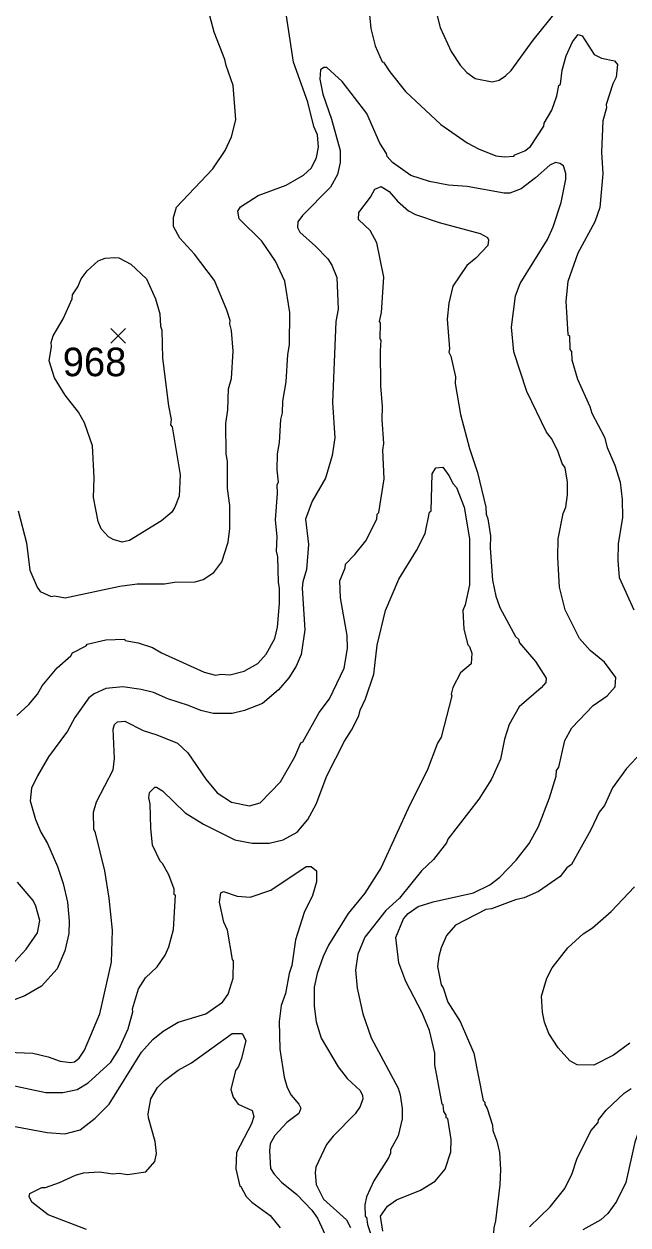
# Model space of a CAD drawing. Extents: x 265.7 to 292.1, y 7676.2 to 7704.2.
# Drawn here: x 276.788 to 278.481, y 7696.84 to 7700.203 of the extents above; entities that cross this region are included whole.
import ezdxf
from ezdxf.enums import TextEntityAlignment as Align

# ---------------------------------------------------------------- set-up
doc = ezdxf.new("R2010")
doc.units = 0
doc.header["$LTSCALE"] = 0.032
for name, color, linetype, lineweight in [('1', 7, 'Continuous', 25), ('2', 7, 'Continuous', 13), ('21', 7, 'Continuous', 25)]:
    doc.layers.add(name, color=color, linetype=linetype, lineweight=lineweight)
doc.layers.add('61', color=7, linetype='Continuous')

msp = doc.modelspace()

# ---------------------------------------------------------------- linework, layer by layer
at = {"layer": '1'}
for points in [[(278.3115, 7698.9198), (278.3051, 7698.9605), (278.2971, 7698.9725), (278.2844, 7699.0076), (278.2668, 7699.0427), (278.2532, 7699.0602), (278.1982, 7699.1735), (278.1615, 7699.2853), (278.1551, 7699.3539), (278.1663, 7699.4417), (278.179, 7699.4768), (278.2556, 7699.5997), (278.2716, 7699.6348), (278.2939, 7699.7034), (278.3067, 7699.7688), (278.3067, 7699.7848), (278.3003, 7699.8063), (278.2907, 7699.8127), (278.278, 7699.8151), (278.262, 7699.8079), (278.2221, 7699.772), (278.1822, 7699.7417), (278.1503, 7699.7297), (278.1344, 7699.7289), (278.0306, 7699.7481), (277.978, 7699.752), (277.9253, 7699.7616), (277.8726, 7699.7792), (277.8216, 7699.8151), (277.8064, 7699.8319), (277.804, 7699.8406), (277.7856, 7699.8694), (277.7489, 7699.9524), (277.6803, 7700.0417), (277.6372, 7700.0816), (277.6284, 7700.0816), (277.6197, 7700.0744), (277.6173, 7700.0489), (277.626, 7700.0066), (277.65, 7699.9364), (277.6747, 7699.8486), (277.6747, 7699.8151), (277.6667, 7699.7816), (277.6476, 7699.7465), (277.5686, 7699.6667), (277.5558, 7699.6491), (277.555, 7699.6332), (277.5614, 7699.6204), (277.6053, 7699.5813), (277.6396, 7699.5454), (277.6508, 7699.5278), (277.6651, 7699.4927), (277.6691, 7699.4049), (277.662, 7699.3698), (277.6532, 7699.1432), (277.6596, 7699.0443), (277.6524, 7698.9948), (277.6332, 7698.931), (277.5957, 7698.8671), (277.5774, 7698.8161), (277.5853, 7698.7458), (277.5806, 7698.6756), (277.5694, 7698.6405), (277.5678, 7698.6229), (277.5758, 7698.5064), (277.5654, 7698.4378), (277.551, 7698.4043), (277.5303, 7698.3724), (277.5016, 7698.3381), (277.4569, 7698.3006), (277.4066, 7698.2806), (277.3715, 7698.2726), (277.3188, 7698.2726), (277.2837, 7698.2806), (277.2494, 7698.295), (277.1912, 7698.3133), (277.1513, 7698.3309), (277.1162, 7698.3397), (277.0651, 7698.3468), (277.0172, 7698.342), (276.9853, 7698.3277), (276.9701, 7698.3165), (276.931, 7698.2607), (276.9103, 7698.2224), (276.8568, 7698.1506), (276.8257, 7698.0979), (276.8089, 7698.0628), (276.8057, 7698.0277), (276.8201, 7697.975), (276.8353, 7697.9399), (276.8544, 7697.908), (276.8823, 7697.8441), (276.8983, 7697.7963), (276.9103, 7697.7436), (276.9151, 7697.6909)], [(278.2892, 7698.6261), (278.2844, 7698.7091), (278.286, 7698.7618), (278.2995, 7698.832), (278.3067, 7698.8496), (278.3115, 7698.8847), (278.3115, 7698.9198)], [(277.7944, 7696.8227), (277.788, 7696.8642), (277.8072, 7696.8922), (277.8327, 7696.9105), (277.8998, 7696.9376), (277.9412, 7696.9624), (277.9692, 7696.9959), (277.9851, 7697.0446), (277.9859, 7697.0797), (277.9764, 7697.1379), (277.9716, 7697.1403), (277.9716, 7697.1475), (277.9652, 7697.1579), (277.9636, 7697.1762), (277.9604, 7697.1778), (277.9396, 7697.2888), (277.9396, 7697.3207), (277.9253, 7697.3845), (277.9045, 7697.434), (277.8583, 7697.5218), (277.8391, 7697.5744), (277.8303, 7697.6446), (277.8519, 7697.6973), (277.8654, 7697.7125), (277.8934, 7697.7316), (277.9349, 7697.7452), (278.0482, 7697.7699), (278.0945, 7697.7923), (278.1224, 7697.8138), (278.1679, 7697.8617), (278.2046, 7697.908), (278.2301, 7697.9559), (278.2612, 7698.0356), (278.2804, 7698.0971), (278.2812, 7698.113), (278.2876, 7698.1218), (278.3043, 7698.1968), (278.3243, 7698.2319), (278.3841, 7698.295), (278.4232, 7698.3221), (278.4456, 7698.3468), (278.4471, 7698.3732), (278.4152, 7698.4155), (278.3753, 7698.449), (278.3458, 7698.4825), (278.3051, 7698.5623), (278.2892, 7698.6261)], [(276.9151, 7697.6909), (276.9135, 7697.6558), (276.9031, 7697.6079), (276.8815, 7697.5569), (276.8369, 7697.5082), (276.7906, 7697.4818), (276.7555, 7697.4683)], [(278.8637, 7697.5186), (278.8158, 7697.4938), (278.7727, 7697.4611), (278.7472, 7697.4276), (278.7049, 7697.3574), (278.6786, 7697.3223), (278.5621, 7697.2002), (278.5405, 7697.1675), (278.5174, 7697.1196), (278.5006, 7697.0717), (278.4751, 7696.9584), (278.4495, 7696.9057), (278.4248, 7696.8722), (278.4057, 7696.8547), (278.3546, 7696.8259)]]:
    msp.add_lwpolyline(points, dxfattribs=at)
at = {"layer": '2'}
for points in [[(277.745, 7700.4838), (277.7418, 7700.4662), (277.7426, 7700.3737), (277.7601, 7700.1901), (277.7729, 7700.1423), (277.792, 7700.0968), (277.796, 7700.096)], [(277.3651, 7698.8544), (277.3587, 7698.9022), (277.3587, 7698.9788), (277.3547, 7698.998), (277.3539, 7699.0842), (277.3595, 7699.1225), (277.3619, 7699.1815), (277.3699, 7699.2102), (277.3747, 7699.2869), (277.3699, 7699.3443), (277.3651, 7699.3635), (277.3659, 7699.373), (277.3571, 7699.4018), (277.322, 7699.4847), (277.2662, 7699.5582), (277.2247, 7699.6036), (277.2071, 7699.6364), (277.2071, 7699.6611), (277.2159, 7699.6898), (277.318, 7699.7975), (277.3523, 7699.8486), (277.3699, 7699.8869), (277.3819, 7699.9348), (277.3747, 7700.0306), (277.3547, 7700.0864), (277.3516, 7700.104), (277.3212, 7700.1806), (277.2965, 7700.2763)], [(277.9365, 7700.2659), (277.9548, 7700.1933), (277.9859, 7700.1263), (278.0107, 7700.088), (278.0298, 7700.0672), (278.053, 7700.0505), (278.1008, 7700.0409), (278.12, 7700.0457), (278.1383, 7700.0577), (278.1535, 7700.0728), (278.2157, 7700.1582), (278.282, 7700.2396)], [(276.7682, 7698.2663), (276.8018, 7698.2974), (276.8257, 7698.3261), (276.8393, 7698.35), (276.8816, 7698.4003), (276.9191, 7698.4338), (276.9238, 7698.4418), (276.9622, 7698.4618), (276.9653, 7698.4665), (277.0172, 7698.4785), (277.0699, 7698.4801), (277.0715, 7698.4769), (277.1082, 7698.4705), (277.1481, 7698.457), (277.1736, 7698.4418), (277.2933, 7698.3875), (277.3252, 7698.3796), (277.3412, 7698.382), (277.3651, 7698.3804), (277.405, 7698.3907), (277.4433, 7698.4123), (277.4673, 7698.4386), (277.4912, 7698.4825), (277.4992, 7698.5144), (277.5048, 7698.5799), (277.5048, 7698.6229), (277.5016, 7698.6389), (277.5, 7698.7107), (277.496, 7698.7267), (277.4976, 7698.7666), (277.4936, 7698.8145), (277.4992, 7698.8879), (277.4976, 7698.9134), (277.5016, 7698.9198), (277.4976, 7698.9549), (277.4984, 7698.9996), (277.504, 7699.0315), (277.508, 7699.0953), (277.5127, 7699.1145), (277.5135, 7699.1472), (277.5231, 7699.2007), (277.5279, 7699.2773), (277.5327, 7699.3044), (277.5335, 7699.3954), (277.5191, 7699.4832), (277.4936, 7699.539), (277.4545, 7699.5949), (277.3914, 7699.6571), (277.3875, 7699.6786), (277.3954, 7699.6914), (277.4449, 7699.7225), (277.5231, 7699.7513), (277.5718, 7699.78), (277.5941, 7699.8007), (277.6085, 7699.8295), (277.6141, 7699.8582), (277.6109, 7699.8925), (277.6005, 7699.9156), (277.5838, 7699.9843), (277.5439, 7700.096), (277.5231, 7700.2316)], [(277.796, 7700.096), (277.8136, 7700.0689), (277.8575, 7700.0138), (277.9564, 7699.922), (278.0306, 7699.8702), (278.0625, 7699.8534), (278.1112, 7699.8342), (278.136, 7699.8311), (278.1615, 7699.8326), (278.1639, 7699.8366), (278.1918, 7699.8478), (278.2078, 7699.8598), (278.2453, 7699.9172), (278.2461, 7699.9252), (278.2676, 7699.9619), (278.282, 7700.0018), (278.2876, 7700.0305), (278.2923, 7700.0345), (278.2971, 7700.0736), (278.3083, 7700.1135), (278.3259, 7700.1534), (278.3418, 7700.1734), (278.353, 7700.1702), (278.3865, 7700.1175), (278.4073, 7700.1072), (278.4432, 7700.1), (278.4519, 7700.0896), (278.4487, 7700.0545), (278.4392, 7700.0353), (278.42, 7699.9779), (278.4208, 7699.9683), (278.4112, 7699.9316), (278.4073, 7699.8438), (278.4112, 7699.7832), (278.4025, 7699.689), (278.3881, 7699.6491), (278.341, 7699.5614), (278.3123, 7699.4816), (278.3067, 7699.4273), (278.3131, 7699.3339), (278.3171, 7699.3299), (278.3179, 7699.2916), (278.3227, 7699.2861), (278.3243, 7699.2629), (278.3402, 7699.2087), (278.3745, 7699.132), (278.3801, 7699.1129), (278.4152, 7699.0459), (278.4232, 7699.0171), (278.4448, 7698.9677), (278.4591, 7698.9198), (278.4655, 7698.8719), (278.4663, 7698.8208), (278.4543, 7698.7474), (278.4527, 7698.7011), (278.4567, 7698.6533), (278.4982, 7698.5623)], [(277.2183, 7698.1888), (277.247, 7698.1625), (277.2981, 7698.0883), (277.33, 7698.05), (277.3699, 7698.0237), (277.4202, 7698.0133), (277.4505, 7698.0221), (277.5072, 7698.0811), (277.5471, 7698.1506), (277.5638, 7698.1905), (277.5694, 7698.1928), (277.6157, 7698.275), (277.6444, 7698.3133), (277.6859, 7698.3995), (277.6947, 7698.4538), (277.6939, 7698.4905), (277.6755, 7698.5958), (277.6739, 7698.6437), (277.6883, 7698.6804), (277.6891, 7698.69), (277.7154, 7698.7171), (277.7465, 7698.7562), (277.7769, 7698.8168), (277.7785, 7698.8304), (277.7825, 7698.8352), (277.7976, 7698.9294), (277.7944, 7699.0092), (277.7968, 7699.0283), (277.792, 7699.0953), (277.7936, 7699.132), (277.7888, 7699.1895), (277.7872, 7699.2876), (277.7896, 7699.318), (277.7864, 7699.3212), (277.7872, 7699.3666), (277.7848, 7699.3698), (277.7904, 7699.3954), (277.7968, 7699.4943), (277.7769, 7699.5901), (277.7585, 7699.6244), (277.7258, 7699.6555), (277.7266, 7699.6755), (277.7593, 7699.7178), (277.7713, 7699.7409), (277.7896, 7699.7481), (277.812, 7699.7337), (277.8351, 7699.7066), (277.8662, 7699.6794), (277.8854, 7699.6699), (277.9524, 7699.6475), (278.0673, 7699.6164), (278.0873, 7699.6052), (278.0905, 7699.5988), (278.0889, 7699.5829), (278.0546, 7699.547), (278.0298, 7699.527), (277.9907, 7699.4688), (277.9788, 7699.4209), (277.9748, 7699.3762), (277.9811, 7699.2932), (277.9795, 7699.2845), (277.9851, 7699.2725), (277.9979, 7699.215), (277.9971, 7699.1959), (278.0115, 7699.1097), (278.037, 7699.0139), (278.0593, 7698.9469), (278.0833, 7698.8496), (278.0841, 7698.8304), (278.0889, 7698.8177), (278.0961, 7698.7698), (278.0953, 7698.7363), (278.1016, 7698.6453), (278.1112, 7698.6006), (278.1224, 7698.5687), (278.1663, 7698.4881), (278.1743, 7698.4801), (278.1774, 7698.4697), (278.2221, 7698.4179), (278.2524, 7698.3716), (278.2509, 7698.3588), (278.2381, 7698.3437), (278.1766, 7698.291), (278.1479, 7698.2415), (278.1352, 7698.2), (278.124, 7698.1442), (278.0984, 7698.0883), (278.0633, 7698.0325), (277.9764, 7697.9207), (277.9724, 7697.9104), (277.9365, 7697.8633), (277.9029, 7697.8314), (277.8407, 7697.7548), (277.8024, 7697.7204), (277.7434, 7697.6462)], [(276.722, 7697.2377), (276.8496, 7697.2113), (276.8975, 7697.2113), (276.9374, 7697.2193), (276.9685, 7697.2377), (277.0316, 7697.2959), (277.0539, 7697.331), (277.0802, 7697.3893), (277.093, 7697.4372), (277.0922, 7697.4452), (277.109, 7697.501), (277.1289, 7697.5321), (277.1616, 7697.5625), (277.184, 7697.5952), (277.1944, 7697.6191), (277.2071, 7697.667), (277.2127, 7697.7635), (277.2095, 7697.7643), (277.2087, 7697.7803), (277.1944, 7697.8202), (277.1768, 7697.8521), (277.1696, 7697.8585), (277.1481, 7697.9032), (277.1433, 7697.9511), (277.1417, 7698.0197), (277.1377, 7698.0356), (277.1401, 7698.0508), (277.1553, 7698.066), (277.16, 7698.066), (277.176, 7698.0556), (277.2398, 7697.9942), (277.2917, 7697.9622), (277.3795, 7697.9183), (277.4274, 7697.9088), (277.4752, 7697.9088), (277.5151, 7697.9183), (277.5542, 7697.9399), (277.5838, 7697.975), (277.6069, 7698.0181), (277.6372, 7698.0979), (277.6867, 7698.1944), (277.7066, 7698.2256), (277.7266, 7698.2655), (277.7306, 7698.2814), (277.7457, 7698.3133), (277.7689, 7698.382), (277.7785, 7698.4634), (277.8016, 7698.5607), (277.8391, 7698.6485), (277.8886, 7698.7283), (277.9125, 7698.7762), (277.9253, 7698.836), (277.9293, 7698.84), (277.9325, 7698.9437), (277.9428, 7698.9605), (277.962, 7698.9621), (277.9795, 7698.9389), (277.9915, 7698.915), (278.0003, 7698.9054), (278.0226, 7698.8496), (278.037, 7698.7618), (278.037, 7698.6325)], [(276.7714, 7698.84), (276.7954, 7698.7506), (276.8049, 7698.674), (276.8249, 7698.6261), (276.8337, 7698.6142), (276.864, 7698.5998), (276.8736, 7698.6014), (276.9039, 7698.5958), (277.0571, 7698.6285), (277.105, 7698.6349), (277.1816, 7698.6349), (277.2103, 7698.6397), (277.2678, 7698.6405)], [(277.2678, 7698.6405), (277.2901, 7698.6477), (277.3204, 7698.6668), (277.3428, 7698.6972), (277.3603, 7698.7522), (277.3651, 7698.7905), (277.3651, 7698.8544)], [(278.037, 7698.6325), (278.025, 7698.5767), (278.0186, 7698.5607), (278.021, 7698.508), (278.0322, 7698.4642), (278.037, 7698.4602), (278.0434, 7698.441)], [(278.0434, 7698.441), (278.0418, 7698.4115), (278.0115, 7698.3859), (277.9899, 7698.3453), (277.9859, 7698.3261), (277.9875, 7698.3213), (277.9572, 7698.2064), (277.9476, 7698.1889), (277.9181, 7698.1123), (277.8702, 7698.0165), (277.7896, 7697.8409), (277.7441, 7697.7691), (277.6971, 7697.7117), (277.642, 7697.6239), (277.6268, 7697.592), (277.6101, 7697.5441), (277.6013, 7697.5058), (277.6013, 7697.4523), (277.6077, 7697.4084), (277.6213, 7697.363), (277.6691, 7697.2824), (277.6939, 7697.2505), (277.7306, 7697.2161), (277.737, 7697.2026), (277.7378, 7697.193), (277.7306, 7697.1714), (277.717, 7697.1515), (277.6548, 7697.0885), (277.6364, 7697.0653), (277.6061, 7697.0015), (277.6045, 7696.9855), (277.6077, 7696.9536), (277.6276, 7696.9121), (277.6923, 7696.8539), (277.7035, 7696.8331)], [(277.038, 7698.2288), (277.0419, 7698.2415), (277.0499, 7698.2487), (277.0707, 7698.2511), (277.1225, 7698.2248), (277.1608, 7698.2128), (277.2183, 7698.1888)], [(276.7188, 7697.3247), (276.8129, 7697.3215), (276.856, 7697.3111), (276.8895, 7697.2983), (276.9191, 7697.2951), (276.9294, 7697.2967), (276.943, 7697.3071), (276.9574, 7697.3294), (277.0012, 7697.4308), (277.0332, 7697.576), (277.0364, 7697.6654), (277.0268, 7697.7548), (277.0148, 7697.8314), (276.9885, 7697.9383), (276.9837, 7697.9479), (276.9829, 7697.9957), (276.9917, 7698.0245), (277.038, 7698.1146), (277.0419, 7698.1458), (277.038, 7698.2288)], [(278.5469, 7698.1928), (278.4775, 7698.1186), (278.4376, 7698.0636), (278.4152, 7698.0149), (278.4009, 7697.9957), (278.3777, 7697.9463), (278.3227, 7697.8497), (278.3099, 7697.8401), (278.2908, 7697.8154), (278.2301, 7697.7739), (278.1902, 7697.7556), (278.1663, 7697.7508), (278.0992, 7697.7252), (278.0825, 7697.7236), (277.9979, 7697.6797), (277.9724, 7697.6502), (277.9572, 7697.6159), (277.9508, 7697.592), (277.9476, 7697.5633), (277.9572, 7697.5122), (277.9628, 7697.5042), (277.9764, 7697.4643), (278.0107, 7697.41), (278.049, 7697.3207), (278.0753, 7697.1882), (278.0801, 7697.1842), (278.0801, 7697.177), (278.0865, 7697.1659), (278.1016, 7697.1196), (278.1024, 7697.1044), (278.1136, 7697.0749), (278.1208, 7697.043), (278.124, 7696.9951)], [(276.7427, 7697.1196), (276.8528, 7697.0988), (276.9023, 7697.0956), (276.9454, 7697.106), (276.9877, 7697.1387), (277.0268, 7697.1786), (277.1177, 7697.3239), (277.1497, 7697.359), (277.1784, 7697.3829), (277.2207, 7697.4076), (277.2981, 7697.4316), (277.3444, 7697.4635), (277.3603, 7697.4867), (277.3747, 7697.5313), (277.3755, 7697.58), (277.3723, 7697.5832), (277.3587, 7697.6654), (277.3484, 7697.6877), (277.3364, 7697.7436), (277.3396, 7697.7699), (277.3476, 7697.7739), (277.3859, 7697.7611), (277.4218, 7697.758), (277.48, 7697.7771), (277.579, 7697.8433), (277.5933, 7697.8441), (277.6085, 7697.8314), (277.6085, 7697.801), (277.5965, 7697.7627), (277.5734, 7697.7149), (277.5494, 7697.6383), (277.5391, 7697.5664), (277.5319, 7697.5441), (277.5215, 7697.4882), (277.5095, 7697.4547), (277.5032, 7697.41), (277.5056, 7697.3318), (277.5175, 7697.2536), (277.5255, 7697.2249), (277.5367, 7697.2034), (277.5582, 7697.1786), (277.5638, 7697.1667), (277.559, 7697.1523), (277.5247, 7697.1268), (277.4912, 7697.0901), (277.4784, 7697.0669)], [(276.7531, 7697.5672), (276.7938, 7697.6119), (276.8257, 7697.6582), (276.8321, 7697.6925), (276.8217, 7697.7324), (276.8137, 7697.7484), (276.7698, 7697.8002)], [(278.4863, 7697.3486), (278.4408, 7697.3159), (278.3857, 7697.2872), (278.3386, 7697.288), (278.3187, 7697.2999), (278.286, 7697.3358), (278.2596, 7697.3757), (278.2477, 7697.4076), (278.2413, 7697.4356), (278.2389, 7697.4811), (278.254, 7697.5313), (278.2684, 7697.5601), (278.3131, 7697.6159), (278.3554, 7697.655), (278.3817, 7697.6718), (278.4344, 7697.7173), (278.4998, 7697.7867)], [(277.7434, 7697.6462), (277.7242, 7697.5984), (277.7178, 7697.5537), (277.7226, 7697.5034), (277.7378, 7697.4308), (277.7617, 7697.3638), (277.8375, 7697.2233)], [(276.963, 7696.8275), (276.856, 7696.8682), (276.8097, 7696.9041), (276.8026, 7696.9201), (276.8049, 7696.9281), (276.8385, 7696.9448), (276.848, 7696.9448), (276.8879, 7696.9584), (276.9326, 7696.9791), (276.955, 7696.9855), (276.9997, 7696.9887), (277.0372, 7696.9831), (277.0547, 7696.9847), (277.0779, 7696.9815), (277.1297, 7696.9887), (277.1545, 7697.0174), (277.16, 7697.0398), (277.1561, 7697.0733), (277.1369, 7697.1403), (277.1361, 7697.1515), (277.1441, 7697.193), (277.1624, 7697.2249), (277.1816, 7697.2441), (277.2199, 7697.2736), (277.2582, 7697.2943), (277.3715, 7697.3757), (277.4002, 7697.3765), (277.4098, 7697.3566), (277.3978, 7697.3063), (277.3891, 7697.284), (277.3811, 7697.2728), (277.3683, 7697.2193), (277.3747, 7697.1978), (277.3883, 7697.1786), (277.4282, 7697.1603), (277.4329, 7697.1435), (277.4258, 7697.1228), (277.3843, 7697.043)], [(277.8375, 7697.2233), (277.8431, 7697.2042), (277.8479, 7697.1659), (277.8479, 7697.1371), (277.8367, 7697.0893), (277.816, 7697.0502), (277.816, 7697.0414), (277.8104, 7697.0278), (277.7689, 7696.9632), (277.7481, 7696.9185), (277.7434, 7696.8962), (277.7442, 7696.8634), (277.7481, 7696.8618), (277.7513, 7696.8411), (277.7769, 7696.7621)], [(278.2054, 7696.8347), (278.2636, 7696.8906), (278.3043, 7696.9416), (278.3251, 7696.9839), (278.3378, 7697.0238), (278.3769, 7697.1036), (278.3977, 7697.1268), (278.3985, 7697.134), (278.42, 7697.1611), (278.4703, 7697.209), (278.4903, 7697.2217)], [(277.4784, 7697.0669), (277.476, 7697.0478), (277.4792, 7696.9983), (277.4896, 7696.9823), (277.5103, 7696.96), (277.5534, 7696.9257), (277.5949, 7696.881)], [(277.3843, 7697.043), (277.3819, 7696.9967), (277.393, 7696.9488), (277.3962, 7696.948), (277.4114, 7696.9201), (277.4266, 7696.9041), (277.4784, 7696.8666)], [(278.124, 7696.9951), (278.1224, 7696.952), (278.1104, 7696.8515), (278.1056, 7696.8323), (278.1016, 7696.7749), (278.0953, 7696.7477), (278.0921, 7696.6504)], [(277.4784, 7696.8666), (277.5064, 7696.8323)], [(277.5949, 7696.881), (277.6109, 7696.8587), (277.638, 7696.8004)]]:
    msp.add_lwpolyline(points, dxfattribs=at)
msp.add_lwpolyline([(277.0157, 7699.5469), (277.0424, 7699.5496), (277.0539, 7699.5478), (277.0874, 7699.5302), (277.1313, 7699.4895), (277.1569, 7699.4337), (277.1688, 7699.3914), (277.1704, 7699.3571), (277.1744, 7699.3459), (277.176, 7699.2677), (277.1928, 7699.1336), (277.2007, 7699.0953), (277.1991, 7699.0802), (277.2031, 7699.0754), (277.2263, 7698.9405), (277.2231, 7698.8807), (277.2111, 7698.8496), (277.2023, 7698.836), (277.1736, 7698.8121), (277.0842, 7698.757), (277.0635, 7698.7522), (277.038, 7698.7594), (277.0252, 7698.7666), (277.0044, 7698.7889), (276.9957, 7698.8097), (276.9829, 7698.8767), (276.9853, 7698.9326), (276.9805, 7699.0219), (276.9574, 7699.0858), (276.9406, 7699.1161), (276.9039, 7699.164), (276.8736, 7699.2118), (276.8584, 7699.2597), (276.8648, 7699.2996), (276.864, 7699.3108), (276.8704, 7699.3299), (276.8983, 7699.3778), (276.923, 7699.4337), (276.9246, 7699.4448), (276.939, 7699.4672), (276.9486, 7699.4895), (276.9653, 7699.5119), (276.9965, 7699.5398)], close=True, dxfattribs=at)
at = {"layer": '21'}
for p, q in [((277.0312, 7699.3508), (277.0724, 7699.3096)), ((277.0724, 7699.3508), (277.0312, 7699.3096))]:
    msp.add_line(p, q, dxfattribs=at)

# ---------------------------------------------------------------- texts
at = {"layer": '61'}
msp.add_text('968', height=0.08, dxfattribs=at).set_placement((276.986, 7699.2167), align=Align.CENTER)

doc.saveas('drawing.dxf')
